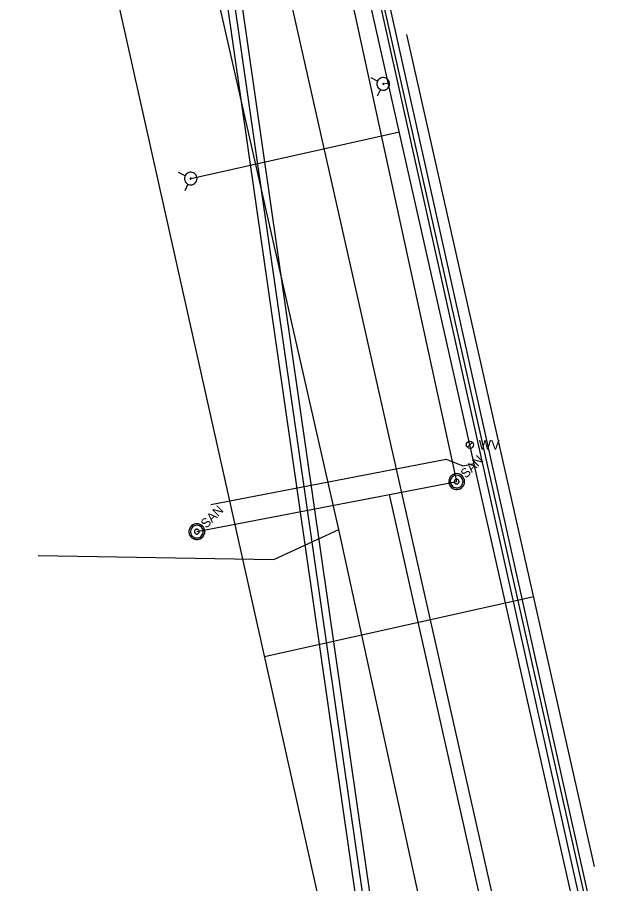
# Model space of a CAD drawing. Extents: x 600849 to 606371, y 330010 to 403088.
# Drawn here: x 604843.6 to 605092, y 338228.9 to 338589.4 of the extents above; entities that cross this region are included whole.
import ezdxf

# ---------------------------------------------------------------- set-up
doc = ezdxf.new("R2010")
doc.units = 0
for name, color, linetype in [('E_UTL_E_UG', 7, 'Continuous'), ('E_UTL_G_UG', 7, 'Continuous'), ('E_UTL_SAN_MH', 7, 'Continuous'), ('E_UTL_SAN_UG', 7, 'Continuous'), ('E_UTL_SAN_UG_MMSD', 7, 'Continuous'), ('E_UTL_SAN_UG_OUTER_LIMITS', 7, 'Continuous'), ('E_UTL_TV_UG', 7, 'Continuous'), ('E_UTL_W', 7, 'Continuous'), ('E_UTL_W_UG', 7, 'Continuous'), ('E_UTL_WHydrant', 7, 'Continuous')]:
    doc.layers.add(name, color=color, linetype=linetype)

# ---------------------------------------------------------------- blocks, each defined once
blk = doc.blocks.new('WV')
at = {"layer": 'E_UTL_W'}
blk.add_line((-8.6, -8.6), (8.6, 8.6), dxfattribs=at)
blk.add_circle((0, 0), 12.2, dxfattribs=at)
blk.add_text('WV', height=32.92, dxfattribs=at).set_placement((30.5, -16.5))

msp = doc.modelspace()

# ---------------------------------------------------------------- linework, layer by layer
at = {"layer": 'E_UTL_E_UG'}
for p, q in [((604977.34, 338376.34), (604875.51, 338824.32)), ((605031.55, 338127.51), (604977.34, 338376.34))]:
    msp.add_line(p, q, dxfattribs=at)
for points in [[(605086.65, 338141.8), (605083.96, 338193.78), (604971.91, 338697.03), (604971.23, 338704.69)], [(604852.21, 338365.42), (604950.22, 338363.75), (604977.34, 338376.34)]]:
    msp.add_lwpolyline(points, dxfattribs=at)
at = {"layer": 'E_UTL_G_UG'}
for p, q in [((605063.85, 338123.62), (604914.69, 338786.08)), ((604946.41, 338323.4), (605058.37, 338348.43))]:
    msp.add_line(p, q, dxfattribs=at)
for points in [[(604985.44, 338110.91), (604985.58, 338148.1), (604843.56, 338783.61)], [(605083.71, 338236.08), (605005.61, 338582.32)]]:
    msp.add_lwpolyline(points, dxfattribs=at)
at = {"layer": 'E_UTL_SAN_MH'}
for points in [[(605028.64, 338398.54), (605028.16, 338398.94), (605027.61, 338399.24), (605027.01, 338399.43), (605026.39, 338399.51), (605025.76, 338399.46), (605025.15, 338399.3), (605024.59, 338399.03), (605024.09, 338398.65), (605023.67, 338398.19), (605023.34, 338397.65), (605023.12, 338397.06), (605023.02, 338396.44), (605023.03, 338395.82), (605023.16, 338395.2), (605023.41, 338394.63), (605023.76, 338394.11), (605024.21, 338393.66), (605024.73, 338393.31), (605025.3, 338393.06), (605025.92, 338392.93), (605026.54, 338392.92), (605027.16, 338393.02), (605027.75, 338393.24), (605028.29, 338393.57), (605028.75, 338393.99), (605029.13, 338394.49), (605029.4, 338395.05), (605029.56, 338395.66), (605029.61, 338396.29), (605029.53, 338396.91), (605029.34, 338397.51), (605029.04, 338398.06), (605028.64, 338398.54)], [(605028.17, 338398.07), (605027.79, 338398.39), (605027.35, 338398.63), (605026.87, 338398.79), (605026.37, 338398.85), (605025.87, 338398.81), (605025.38, 338398.68), (605024.93, 338398.46), (605024.53, 338398.16), (605024.19, 338397.79), (605023.93, 338397.36), (605023.76, 338396.89), (605023.67, 338396.4), (605023.69, 338395.89), (605023.79, 338395.4), (605023.99, 338394.94), (605024.27, 338394.53), (605024.63, 338394.17), (605025.04, 338393.89), (605025.5, 338393.69), (605025.99, 338393.59), (605026.5, 338393.57), (605026.99, 338393.66), (605027.46, 338393.83), (605027.89, 338394.09), (605028.26, 338394.43), (605028.56, 338394.83), (605028.78, 338395.29), (605028.91, 338395.77), (605028.95, 338396.27), (605028.89, 338396.77), (605028.73, 338397.25), (605028.49, 338397.69), (605028.17, 338398.07)], [(605027.01, 338396.91), (605026.86, 338397.03), (605026.7, 338397.12), (605026.52, 338397.18), (605026.33, 338397.2), (605026.14, 338397.18), (605025.96, 338397.14), (605025.79, 338397.05), (605025.64, 338396.94), (605025.51, 338396.8), (605025.42, 338396.64), (605025.35, 338396.46), (605025.32, 338396.28), (605025.32, 338396.09), (605025.36, 338395.91), (605025.44, 338395.73), (605025.54, 338395.58), (605025.68, 338395.44), (605025.83, 338395.34), (605026.01, 338395.26), (605026.19, 338395.22), (605026.38, 338395.22), (605026.56, 338395.25), (605026.74, 338395.32), (605026.9, 338395.42), (605027.04, 338395.54), (605027.15, 338395.69), (605027.24, 338395.86), (605027.28, 338396.04), (605027.3, 338396.23), (605027.27, 338396.42), (605027.22, 338396.6), (605027.13, 338396.76), (605027.01, 338396.91)], [(604920.57, 338377.72), (604920.09, 338378.12), (604919.54, 338378.42), (604918.94, 338378.61), (604918.31, 338378.68), (604917.69, 338378.64), (604917.08, 338378.47), (604916.52, 338378.2), (604916.02, 338377.82), (604915.59, 338377.36), (604915.27, 338376.82), (604915.05, 338376.24), (604914.94, 338375.62), (604914.96, 338374.99), (604915.09, 338374.38), (604915.34, 338373.8), (604915.69, 338373.28), (604916.14, 338372.84), (604916.65, 338372.49), (604917.23, 338372.24), (604917.84, 338372.11), (604918.47, 338372.09), (604919.09, 338372.19), (604919.68, 338372.41), (604920.21, 338372.74), (604920.68, 338373.16), (604921.05, 338373.66), (604921.33, 338374.23), (604921.49, 338374.84), (604921.54, 338375.46), (604921.46, 338376.08), (604921.27, 338376.68), (604920.97, 338377.23), (604920.57, 338377.72)], [(604920.1, 338377.25), (604919.72, 338377.57), (604919.28, 338377.81), (604918.8, 338377.96), (604918.3, 338378.02), (604917.8, 338377.99), (604917.31, 338377.86), (604916.86, 338377.64), (604916.46, 338377.34), (604916.12, 338376.96), (604915.86, 338376.54), (604915.69, 338376.07), (604915.6, 338375.57), (604915.62, 338375.07), (604915.72, 338374.58), (604915.92, 338374.12), (604916.2, 338373.7), (604916.56, 338373.35), (604916.97, 338373.07), (604917.43, 338372.87), (604917.92, 338372.76), (604918.42, 338372.75), (604918.92, 338372.83), (604919.39, 338373.01), (604919.82, 338373.27), (604920.19, 338373.61), (604920.49, 338374.01), (604920.71, 338374.46), (604920.84, 338374.94), (604920.88, 338375.45), (604920.82, 338375.94), (604920.66, 338376.42), (604920.42, 338376.86), (604920.1, 338377.25)], [(604918.94, 338376.08), (604918.79, 338376.2), (604918.63, 338376.29), (604918.45, 338376.35), (604918.26, 338376.37), (604918.07, 338376.36), (604917.89, 338376.31), (604917.72, 338376.23), (604917.57, 338376.12), (604917.44, 338375.98), (604917.35, 338375.82), (604917.28, 338375.64), (604917.25, 338375.45), (604917.25, 338375.26), (604917.29, 338375.08), (604917.37, 338374.91), (604917.47, 338374.75), (604917.61, 338374.62), (604917.76, 338374.51), (604917.93, 338374.44), (604918.12, 338374.4), (604918.31, 338374.4), (604918.49, 338374.43), (604918.67, 338374.49), (604918.83, 338374.59), (604918.97, 338374.72), (604919.08, 338374.87), (604919.16, 338375.04), (604919.21, 338375.22), (604919.23, 338375.41), (604919.2, 338375.59), (604919.15, 338375.77), (604919.06, 338375.94), (604918.94, 338376.08)]]:
    msp.add_lwpolyline(points, dxfattribs=at)
at = {"layer": 'E_UTL_SAN_UG'}
for p, q in [((605026.31, 338396.21), (604979.45, 338612.08)), ((604998.36, 338390.82), (605026.31, 338396.21)), ((604918.24, 338375.38), (604998.36, 338390.82)), ((605067.64, 338083.08), (604998.36, 338390.82))]:
    msp.add_line(p, q, dxfattribs=at)
at = {"layer": 'E_UTL_SAN_UG_MMSD'}
msp.add_line((605016.2, 338023.67), (604854.51, 339147.21), dxfattribs=at)
at = {"layer": 'E_UTL_SAN_UG_OUTER_LIMITS'}
for p, q in [((605012.73, 338026.74), (604851.55, 339146.7)), ((605019.67, 338020.62), (604857.47, 339147.72))]:
    msp.add_line(p, q, dxfattribs=at)
at = {"layer": 'E_UTL_TV_UG'}
msp.add_line((605089.97, 338177.57), (604971.23, 338704.69), dxfattribs=at)
msp.add_lwpolyline([(605091.46, 338177.8), (604939.3, 338859.88), (604936.85, 338860.21)], dxfattribs=at)
at = {"layer": 'E_UTL_W_UG'}
for p, q in [((604995.77, 338561.73), (604997.89, 338562.21)), ((604915.69, 338522.33), (605002.47, 338541.71))]:
    msp.add_line(p, q, dxfattribs=at)
for points in [[(605092.03, 338144.65), (604935.52, 338838.52), (604929.29, 338841.05), (604874.94, 339090.23)], [(604924.06, 338386.69), (605021.94, 338405.55), (605028.94, 338402.83), (605033.59, 338403.72)]]:
    msp.add_lwpolyline(points, dxfattribs=at)
at = {"layer": 'E_UTL_WHydrant'}
for points in [[(604993.44, 338562.88), (604990.72, 338564.21)], [(604994.92, 338564.22), (604994.47, 338564.01), (604994.06, 338563.72), (604993.72, 338563.36), (604993.45, 338562.94), (604993.26, 338562.48), (604993.16, 338561.99), (604993.16, 338561.49), (604993.26, 338561), (604993.44, 338560.54), (604993.71, 338560.12), (604994.05, 338559.76), (604994.46, 338559.47), (604994.91, 338559.26), (604995.4, 338559.14), (604995.89, 338559.11), (604996.39, 338559.18), (604996.86, 338559.35), (604997.29, 338559.59), (604997.67, 338559.92), (604997.98, 338560.31), (604998.21, 338560.75), (604998.35, 338561.23), (604998.4, 338561.73), (604998.35, 338562.22), (604998.21, 338562.7), (604997.98, 338563.15), (604997.68, 338563.54), (604997.3, 338563.87), (604996.87, 338564.12), (604996.4, 338564.28), (604995.91, 338564.35), (604995.41, 338564.33), (604994.92, 338564.22)], [(604995.71, 338561.92), (604995.68, 338561.91), (604995.64, 338561.89), (604995.62, 338561.86), (604995.6, 338561.83), (604995.58, 338561.79), (604995.58, 338561.75), (604995.58, 338561.72), (604995.58, 338561.68), (604995.6, 338561.64), (604995.62, 338561.61), (604995.64, 338561.58), (604995.67, 338561.56), (604995.71, 338561.55), (604995.75, 338561.54), (604995.78, 338561.53), (604995.82, 338561.54), (604995.86, 338561.55), (604995.89, 338561.57), (604995.92, 338561.6), (604995.94, 338561.63), (604995.96, 338561.66), (604995.97, 338561.7), (604995.98, 338561.73), (604995.97, 338561.77), (604995.96, 338561.81), (604995.94, 338561.84), (604995.92, 338561.87), (604995.89, 338561.9), (604995.86, 338561.92), (604995.82, 338561.93), (604995.78, 338561.93), (604995.75, 338561.93), (604995.71, 338561.92)], [(604994.63, 338559.4), (604993.3, 338556.68)], [(604913.36, 338523.47), (604910.63, 338524.8)], [(604914.84, 338524.81), (604914.38, 338524.6), (604913.97, 338524.32), (604913.63, 338523.96), (604913.36, 338523.54), (604913.17, 338523.07), (604913.08, 338522.59), (604913.08, 338522.09), (604913.17, 338521.6), (604913.35, 338521.13), (604913.62, 338520.71), (604913.97, 338520.35), (604914.37, 338520.06), (604914.82, 338519.85), (604915.31, 338519.73), (604915.81, 338519.71), (604916.3, 338519.78), (604916.77, 338519.94), (604917.2, 338520.19), (604917.58, 338520.52), (604917.89, 338520.91), (604918.12, 338521.35), (604918.26, 338521.83), (604918.31, 338522.32), (604918.26, 338522.82), (604918.12, 338523.3), (604917.9, 338523.74), (604917.59, 338524.14), (604917.21, 338524.46), (604916.78, 338524.71), (604916.31, 338524.88), (604915.82, 338524.95), (604915.32, 338524.93), (604914.84, 338524.81)], [(604915.62, 338522.52), (604915.59, 338522.5), (604915.56, 338522.48), (604915.53, 338522.45), (604915.51, 338522.42), (604915.5, 338522.39), (604915.49, 338522.35), (604915.49, 338522.31), (604915.49, 338522.27), (604915.51, 338522.24), (604915.53, 338522.21), (604915.56, 338522.18), (604915.59, 338522.16), (604915.62, 338522.14), (604915.66, 338522.13), (604915.7, 338522.13), (604915.73, 338522.13), (604915.77, 338522.15), (604915.8, 338522.17), (604915.83, 338522.19), (604915.86, 338522.22), (604915.87, 338522.25), (604915.88, 338522.29), (604915.89, 338522.33), (604915.88, 338522.37), (604915.87, 338522.4), (604915.86, 338522.44), (604915.83, 338522.47), (604915.8, 338522.49), (604915.77, 338522.51), (604915.74, 338522.52), (604915.7, 338522.53), (604915.66, 338522.53), (604915.62, 338522.52)], [(604914.55, 338520), (604913.22, 338517.28)]]:
    msp.add_lwpolyline(points, dxfattribs=at)

# ---------------------------------------------------------------- block references
at = {"layer": 'E_UTL_W', "xscale": 0.12188295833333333, "yscale": 0.12188295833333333}
msp.add_blockref('WV', (605031.83, 338411.53), dxfattribs=at)

# ---------------------------------------------------------------- texts
at = {"layer": 'E_UTL_SAN_MH'}
for p in [(605030.2, 338397.35), (604922.13, 338376.53)]:
    msp.add_text('SAN', height=3.849, rotation=45, dxfattribs=at).set_placement(p)

doc.saveas('drawing.dxf')
